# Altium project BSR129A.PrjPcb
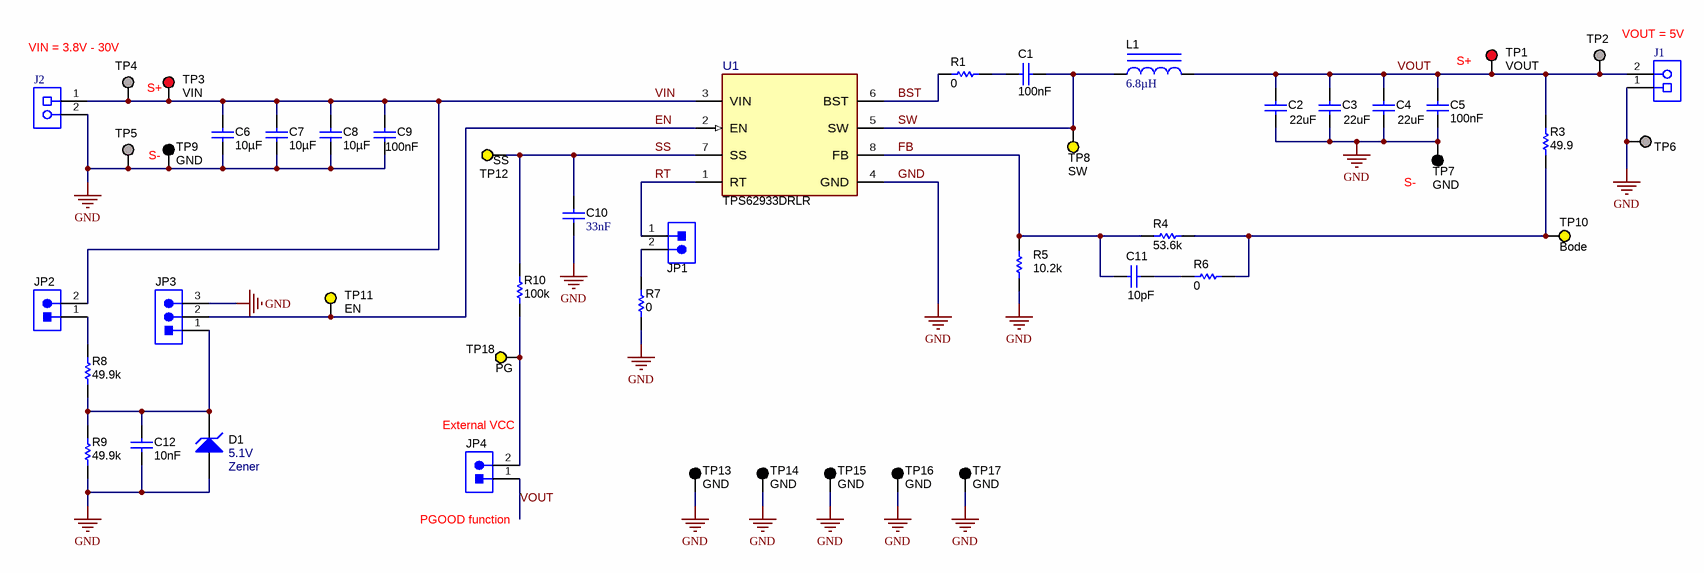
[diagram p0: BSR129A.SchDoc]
A: A; CopyrightYear: 2021; PCB_Layout: Ruby Li; PCB_Rev: A; PRJ_Customer: Public Release; PRJ_Engineer: Ruby Li; PRJ_Number: BSR129; PRJ_Title: BSR129; TechSupport: http://www.ti.com/support; TID: A0489755
2 sheets, 65 parts. Net scope: global (net labels, ports and power ports of the same name join across sheets).
Board file: BSR129A.PcbDoc
Sheets:
  BSR129A.SchDoc
  BSR129A_Hardware.SchDoc

## Sheet BSR129A.SchDoc
size 431 x 279 mm; Date: Not shown in title block; ApprovedBy: Not shown in title block; CheckedBy: Not shown in title block; Author: Not shown in title block; CompanyName: Not shown in title block; Engineer: Not shown in title block; Organization: Not shown in title block; Address1: Not shown in title block; Address2: Not shown in title block; Address3: Not shown in title block; Address4: Not shown in title block; DocumentNumber: 1; Revision: Use project parameter SCH_Rev; SheetNumber: 2; SheetTotal: 3; PageSetup: Record=PageOptions¦CenterHorizontal=True¦CenterVertical=True¦PrintScale=1.00¦XCorrection=1.00¦YCorrection=1.00¦PrintKind=0¦BorderSize=5000000¦LeftOffset=0¦BottomOffset=0¦Orientation=2¦PaperLength=1000¦PaperWidth=1000¦Scale=100¦PaperSource=15¦PrintQuality=600¦MediaType=1¦DitherType=10¦PaperKind=Letter¦PrintScaleMode=1

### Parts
C1  Cap_F: 100nF  [0603]  (hidden comment: C0603C104K5RACAUTO)
C2  ValueDisplayed: 22uF  [1206_180]  (hidden comment: C3216X5R1V226M160AC)
C3  ValueDisplayed: 22uF  [1206_180]  (hidden comment: C3216X5R1V226M160AC)
C4  ValueDisplayed: 22uF  [1206_180]  (hidden comment: C3216X5R1V226M160AC)
C5  Cap_F: 100nF  [0603]  (hidden comment: C0603C104K5RACAUTO)
C6  ValueDisplayed: 10µF  [1206_190]  (hidden comment: CGA5L1X7R1H106K160AC)
C7  ValueDisplayed: 10µF  [1206_190]  (hidden comment: CGA5L1X7R1H106K160AC)
C8  ValueDisplayed: 10µF  [1206_190]  (hidden comment: CGA5L1X7R1H106K160AC)
C9  Cap_F: 100nF  [0603]  (hidden comment: C0603C104K5RACAUTO)
C10  Cap_F: 33nF  [0603]  (hidden comment: 06035C333JAT2A)
C11  ValueDisplayed: 10pF  [0603]  (hidden comment: C0603C100J5GACTU)
C12  Cap_F: 10nF  [0603]  (hidden comment: C0603C103J5RACTU)
D1  Zener  value 5.1V  [SOD-323]
J1  ED120/2DS  [On-Shore_ED120_2DS]  (value not drawn)
J2  ED120/2DS  [On-Shore_ED120_2DS]  (value not drawn)
JP1  PBC02SAAN  [Sullins_PBC02SAAN]  (value not drawn)
JP2  PBC02SAAN  [Sullins_PBC02SAAN]  (value not drawn)
JP3  PEC03SAAN  [CONN_PEC03SAAN]  (value not drawn)
JP4  PBC02SAAN  [Sullins_PBC02SAAN]  (value not drawn)
L1  ValueDisplayed: 6.8µH  [WE-XHMI_6060]  (hidden comment: 74439346068)
R1  ValueDisplayed: 0  [0603]  (hidden comment: RC0603JR-070RL)
R3  ValueDisplayed: 49.9  [0603]  (hidden comment: RC0603FR-0749R9L)
R4  ValueDisplayed: 53.6k  [0603]  (hidden comment: RC0603FR-0753K6L)
R5  ValueDisplayed: 10.2k  [0603]  (hidden comment: RC0603FR-0710K2L)
R6  ValueDisplayed: 0  [0603]  (hidden comment: RC0603JR-070RL)
R7  ValueDisplayed: 0  [0603]  (hidden comment: RC0603JR-070RL)
R8  ValueDisplayed: 49.9k  [0603]  (hidden comment: RC0603FR-0749K9L)
R9  ValueDisplayed: 49.9k  [0603]  (hidden comment: RC0603FR-0749K9L)
R10  ValueDisplayed: 100k  [0603]  (hidden comment: RC0603FR-07100KL)
TP1  VOUT  [Keystone5010]
TP2  1502-2  [Keystone1502-2]  (value not drawn)
TP3  VIN  [Keystone5010]
TP4  1502-2  [Keystone1502-2]  (value not drawn)
TP5  1502-2  [Keystone1502-2]  (value not drawn)
TP6  1502-2  [Keystone1502-2]  (value not drawn)
TP7  GND  [Keystone5011]
TP8  SW  [Keystone5014]
TP9  GND  [Keystone5011]
TP10  Bode  [Keystone5014]
TP11  EN  [Keystone5014]
TP12  SS  [Keystone5014]
TP13  GND  [Keystone5011]
TP14  GND  [Keystone5011]
TP15  GND  [Keystone5011]
TP16  GND  [Keystone5011]
TP17  GND  [Keystone5011]
TP18  PG  [Keystone5014]
U1  TPS62933DRLR  [DRL0008A-MFG]

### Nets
GND: C2.2 C3.2 C4.2 C5.2 C6.2 C7.2 C8.2 C9.2 C10.2 C12.2 D1.2(A) J1.1 J2.2 JP3.3 R5.1 R7.1 R9.1 TP5.1 TP6.1 TP7.1 TP9.1 TP13.1 TP14.1 TP15.1 TP16.1 TP17.1 U1.4(GND)
BST: R1.1 U1.6(BST)
EN: JP3.2 TP11.1 U1.2(EN)
FB: C11.2 R4.1 R5.2 U1.8(FB)
RT: JP1.1 U1.1(RT)
SS: C10.1 R10.2 TP12.1 U1.7(SS)
SW: C1.1 L1.1 TP8.1 U1.5(SW)
VIN: C6.1 C7.1 C8.1 C9.1 J2.1 JP2.2 TP3.1 TP4.1 U1.3(VIN)
VOUT: C2.1 C3.1 C4.1 C5.1 J1.2 JP4.1 L1.2 R3.2 TP1.1 TP2.1
NetC1_2: C1.2 R1.2
NetC11_1: C11.1 R6.1
NetC12_1: C12.1 D1.1(K) JP3.1 R8.1 R9.2
NetJP1_2: JP1.2 R7.2
NetJP2_1: JP2.1 R8.2
NetJP4_2: JP4.2 R10.1 TP18.1
NetR3_1: R3.1 R4.2 R6.2 TP10.1

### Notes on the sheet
- VIN = 3.8V - 30V
- (near TP3) S+
- (near TP1) S+
- VOUT = 5V
- (near TP9) S-
- (near TP7) S-
- (near JP4) External VCC
- (near JP4) PGOOD function

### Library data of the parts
C1 C5 C9 = CMP-0079602-1: CAP, CERM, 0.1 µF, 50 V,+/- 10%, X7R, AEC-Q200 Grade 1, 0603; Manufacturer: Kemet; TaMin_C: -55°C; Polarized: N; SizeAreaWB_mm2: 4.68; U/M: EA; Value: 0.1uF; TaMax_C: 125°C; SizeZ_mm: 1; SizeX_mm: 1.6; SizeY_mm: 0.8; Value2: 50V; SizeArea_mm2: 1.28; AEC Qualified: Y; AEC Category: Q200; ValueDisplayed: 0.1µF
C2-C4 = CMP-0008667-2: CAP, CERM, 22 uF, 35 V, +/- 20%, X5R, 1206; Manufacturer: TDK; TaMin_C: -55°C; ESR_ohm: 2.398m; Polarized: N; SizeAreaWB_mm2: 10.92; Value1: 0.002398 ohm; U/M: EA; Value: 22uF; TaMax_C: 85°C; SizeZ_mm: 1.8; SizeX_mm: 3.2; SizeY_mm: 1.6; Value2: 35V; SizeArea_mm2: 5.12; Cap_F: 22µF; IRMS_A: 4.68507A; AEC Category: Q200
C6-C8 = CMP-0085950-1: CAP, CERM, 10 µF, 50 V,+/- 10%, X7R, AEC-Q200 Grade 1, 1206; Manufacturer: TDK; SizeZ_mm: 1.9; Value: 10uF; Value2: 50V; Cap_Case: 1206; AEC Grade: 1; TaMin_C: -55°C; U/M: EA; SizeArea_mm2: 5.12; TaMax_C: 125°C; AEC Qualified: Y; AEC Category: Q200; SizeX_mm: 3.2; SizeY_mm: 1.6; Polarized: N; SizeAreaWB_mm2: 10.92
C10 = CMP-0006806-1: CAP, CERM, 0.033 uF, 50 V, +/- 5%, X7R, 0603; Manufacturer: AVX; TaMin_C: -55°C; Polarized: N; SizeAreaWB_mm2: 4.68; Value1: Unknown; U/M: EA; TaMax_C: 125°C; SizeZ_mm: 1; SizeX_mm: 1.6; SizeY_mm: 0.8; Value2: 50V; SizeArea_mm2: 1.28; AEC Category: Q200
C11 = CMP-0006839-4: CAP, CERM, 10 pF, 50 V, +/- 5%, C0G/NP0, 0603; Manufacturer: Kemet; TaMin_C: -55°C; Polarized: N; SizeAreaWB_mm2: 4.68; Value1: Unknown; U/M: EA; Value: 10pF; TaMax_C: 125°C; SizeZ_mm: 1; SizeX_mm: 1.6; SizeY_mm: 0.8; Value2: 50V; SizeArea_mm2: 1.28; AEC Category: Q200
C12 = CMP-0006850-4: CAP, CERM, 0.01 uF, 50 V, +/- 5%, X7R, 0603; Manufacturer: Kemet; TaMin_C: -55°C; Polarized: N; SizeAreaWB_mm2: 4.68; Value1: Unknown; U/M: EA; Value: 0.01uF; TaMax_C: 125°C; SizeZ_mm: 1; SizeX_mm: 1.6; SizeY_mm: 0.8; Value2: 50V; SizeArea_mm2: 1.28; AEC Category: Q200
D1 = CMP-0005854-3: Diode, Zener, 5.1 V, 200 mW, SOD-323; PartNumber: MMSZ5231BS-7-F; Manufacturer: Diodes Inc.; Power_W: 200mW; Value1: 0.2W; RJA_CperW: 350; SizeAreaWB_mm2: 8.695; SizeArea_mm2: 3.645; SizeX_mm: 2.7; SizeY_mm: 1.35; SizeZ_mm: 1; AEC Category: Q101
J1 J2 = CMP-0074910-1: Terminal Block, 5.08 mm, 2x1, Brass, TH; Manufacturer: On-Shore Technology; Pitch_mm: 5.08; Gender: Female; Shrouded: N; Row_Count: 1; Current_A: 15A; Voltage_V: 300V; Cert_CULUS: Y; CNHeader: False; CT: True; Green_Lifecycle: Not Set; Green_REACh: Incomplete
JP1 JP2 JP4 = CMP-0054566-1: Header, 100mil, 2x1, Gold, TH; Manufacturer: Sullins Connector Solutions; CNHeader: TRUE; Current_A: 3A; Green_Lifecycle: Active; Shrouded: N; Gender: Male; Green_REACh: Passed; Voltage_V: 1.8kV; Row_Count: 1; Pitch_mm: 2.54; CT: FALSE; Cert_UL: Y
JP3 = CMP-0002338-1: Header, 100mil, 3x1, Tin, TH; Manufacturer: Sullins Connector Solutions; Pitch_mm: 2.54; Gender: Male; Shrouded: N; Row_Count: 1; Current_A: 3A; Voltage_V: 1.8kV; Cert_UL: Y; CNHeader: TRUE; CT: FALSE; Green_Lifecycle: Not Set; Green_REACh: Incomplete
L1 = CMP-0085369-1: Inductor, Shielded, Hyperflux, 6.8 µH, 6.5 A, 0.01936 ohm, SMD; Manufacturer: Wurth Elektronik; AEC Category: Q200; Imax_A: 6.5A; SizeY_mm: 6.45; Isat: 10A @ 30% inductance drop; SizeArea_mm2: 42.8925; Irms: 6.5A @ 40C rise; SizeX_mm: 6.65; Value: 6.8uH; AEC Qualified: N; SizeZ_mm: 6.1; SizeAreaWB_mm2: 73.0925
R1 R6 R7 = CMP-0025885-5: RES, 0, 5%, 0.1 W, 0603; Manufacturer: Yageo; Power_W: 100mW; TempCo: 200 ppm/C; Value_Code: 0000; Value: 0; EIA_Code: E24; SizeX_mm: 1.6; SizeZ_mm: 1; Value2: 0.1W; SizeArea_mm2: 1.28; AEC Qualified: N; VDC_V: 75V; AEC Category: Q200; SizeY_mm: 0.8; SizeAreaWB_mm2: 4.68
R3 = CMP-0023143-5: RES, 49.9, 1%, 0.1 W, 0603; Manufacturer: Yageo; Power_W: 100mW; TempCo: 100 ppm/C; Value_Code: 49R9; Value: 49.9; EIA_Code: E96; SizeX_mm: 1.6; SizeY_mm: 0.8; SizeZ_mm: 1; Value2: 0.1W; SizeArea_mm2: 1.28; AEC Qualified: N; VDC_V: 75V; AEC Category: Q200; SizeAreaWB_mm2: 4.68
R4 = CMP-0023176-5: RES, 53.6 k, 1%, 0.1 W, 0603; Manufacturer: Yageo; Power_W: 100mW; TempCo: 100 ppm/C; Value_Code: 53k6; Value: 53.6k; EIA_Code: E96; SizeX_mm: 1.6; SizeY_mm: 0.8; SizeZ_mm: 1; Value2: 0.1W; SizeArea_mm2: 1.28; AEC Qualified: N; VDC_V: 75V; AEC Category: Q200; SizeAreaWB_mm2: 4.68
R5 = CMP-0022743-5: RES, 10.2 k, 1%, 0.1 W, 0603; Manufacturer: Yageo; Power_W: 100mW; TempCo: 100 ppm/C; Value_Code: 10k2; Value: 10.2k; EIA_Code: E96; SizeX_mm: 1.6; SizeY_mm: 0.8; SizeZ_mm: 1; Value2: 0.1W; SizeArea_mm2: 1.28; AEC Qualified: N; VDC_V: 75V; AEC Category: Q200; SizeAreaWB_mm2: 4.68
R8 R9 = CMP-0023142-5: RES, 49.9 k, 1%, 0.1 W, 0603; Manufacturer: Yageo; Power_W: 100mW; TempCo: 100 ppm/C; Value_Code: 49k9; Value: 49.9k; EIA_Code: E96; SizeX_mm: 1.6; SizeY_mm: 0.8; SizeZ_mm: 1; Value2: 0.1W; SizeArea_mm2: 1.28; AEC Qualified: N; VDC_V: 75V; AEC Category: Q200; SizeAreaWB_mm2: 4.68
R10 = CMP-0022735-5: RES, 100 k, 1%, 0.1 W, 0603; Manufacturer: Yageo; Power_W: 100mW; TempCo: 100 ppm/C; Value: 100k; EIA_Code: E96; SizeX_mm: 1.6; SizeY_mm: 0.8; SizeZ_mm: 1; Value2: 0.1W; SizeArea_mm2: 1.28; AEC Qualified: N; VDC_V: 75V; AEC Category: Q200; SizeAreaWB_mm2: 4.68
TP1 TP3 = CMP-0055147-1: Test Point, Multipurpose, Red, TH; Manufacturer: Keystone; PartNumber: 5010; CNHeader: FALSE; Green_Lifecycle: Active; Green_REACh: Passed; ContactFinish: Silver; CT: TRUE
TP2 TP4-TP6 = CMP-0055113-1: Terminal, Turret, TH, Double; Manufacturer: Keystone; CompType: Turret Terminal; CNHeader: FALSE; Green_Lifecycle: Active; Green_REACh: Passed
TP7 TP9 TP13-TP17 = CMP-0055148-1: Test Point, Multipurpose, Black, TH; Manufacturer: Keystone; PartNumber: 5011; CNHeader: FALSE; Green_Lifecycle: Active; Green_REACh: Passed; ContactFinish: Silver; CT: TRUE
TP8 TP10-TP12 TP18 = CMP-0055151-1: Test Point, Multipurpose, Yellow, TH; Manufacturer: Keystone; PartNumber: 5014; CNHeader: FALSE; Green_Lifecycle: Active; Green_REACh: Passed; ContactFinish: Silver; CT: TRUE
U1 = CMP-0090998-1: 3.8-V to 30-V Input, 3-A/2-A, 300kHz-2.2MHz, Low IQ Synchronous Buck Converter in SOT583 Package; Manufacturer: Texas Instruments; Output Voltage: 0.8-22V; Max Supply Voltage: 30V; TJmax_C: +150°C; Max Duty Cycle: 98%; AEC Qualified: No; Switching Frequency: 310-2100kHz; Output Type: AdjustableProgrammable; Number Of Outputs: 1; SizeZ_mm: 0.6mm; Min Supply Voltage: 3.8V; Standoff Height: 0mm; Nominal Supply Current: 12-250uA

## Sheet BSR129A_Hardware.SchDoc
size 431 x 279 mm; Date: Not shown in title block; ApprovedBy: Not shown in title block; CheckedBy: Not shown in title block; Author: Not shown in title block; CompanyName: Not shown in title block; Engineer: Not shown in title block; Organization: Not shown in title block; Address1: Not shown in title block; Address2: Not shown in title block; Address3: Not shown in title block; Address4: Not shown in title block; DocumentNumber: 1; Revision: Use project parameter SCH_Rev; SheetNumber: 1; SheetTotal: 2; PageSetup: Record=PageOptions¦CenterHorizontal=True¦CenterVertical=True¦PrintScale=1.00¦XCorrection=1.00¦YCorrection=1.00¦PrintKind=0¦BorderSize=5000000¦LeftOffset=0¦BottomOffset=0¦Orientation=2¦PaperLength=1000¦PaperWidth=1000¦Scale=100¦PaperSource=15¦PrintQuality=600¦MediaType=1¦DitherType=10¦PaperKind=Letter¦PrintScaleMode=1
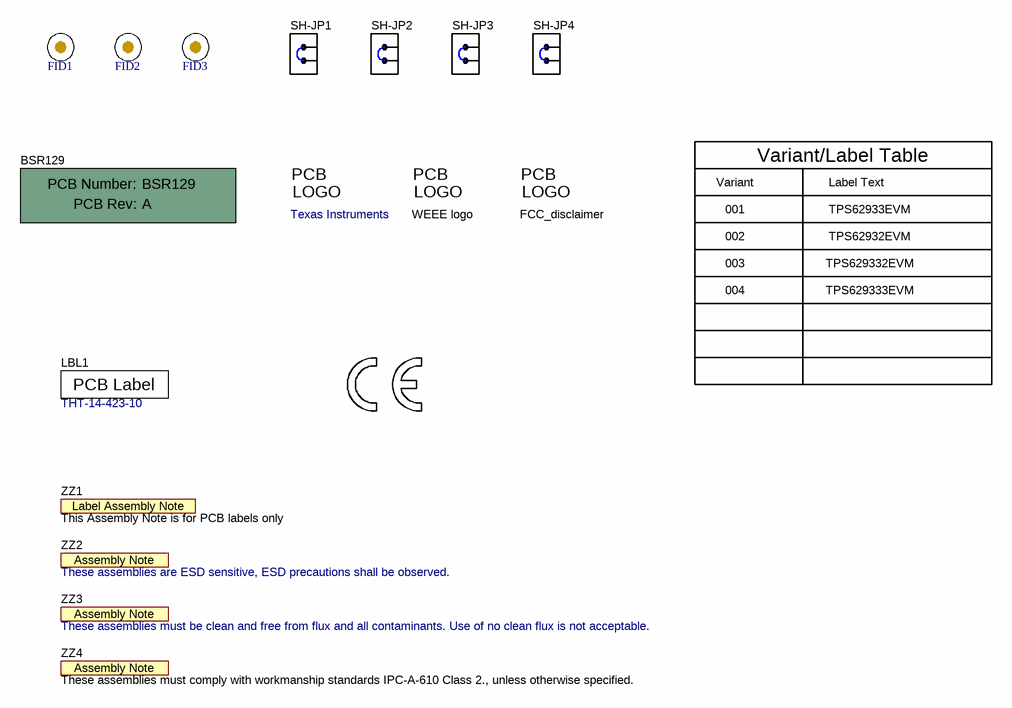
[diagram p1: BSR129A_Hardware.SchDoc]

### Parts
!PCB1  PartNumber: BSR129  (hidden comment: Printed Circuit Board)  (mechanical)
FID1  Fiducial  [Fiducial10-20]  (value not drawn)
FID2  Fiducial  [Fiducial10-20]  (value not drawn)
FID3  Fiducial  [Fiducial10-20]  (value not drawn)
LBL1  THT-14-423-10  [Label_650x200]
Logo1  Texas Instruments  [TI_Stacked_Overlay_Small]  (no BOM)
Logo2  WEEE logo  [WEEE_Minimum]  (no BOM)
Logo3  FCC disclaimer  [FCC_disclaimer]  (value not drawn)  (no BOM)
LOGO4  CE Mark  [CE_Mark_5mm]  (value not drawn)  (no BOM)
SH-JP1  SNT-100-BK-G  [SNT-100-BK-G]  (value not drawn)
SH-JP2  SNT-100-BK-G  [SNT-100-BK-G]  (value not drawn)
SH-JP3  SNT-100-BK-G  [SNT-100-BK-G]  (value not drawn)
SH-JP4  SNT-100-BK-G  [SNT-100-BK-G]  (value not drawn)
ZZ1  This Assembly Note is for PCB labels only  [AssemblyNoteLabel]  (no BOM)
ZZ2  These assemblies are ESD sensitive, ESD precautions shall be observed.  [AssemblyNote]  (no BOM)
ZZ3  These assemblies must be clean and free from flux and all contaminants. Use of no clean flux is not acceptable.  [AssemblyNote]  (no BOM)
ZZ4  These assemblies must comply with workmanship standards IPC-A-610 Class 2., unless otherwise specified.  [AssemblyNote]  (no BOM)

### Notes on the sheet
- Variant
- 001
- Variant/Label Table
- Label Text
- TPS62933EVM
- 002
- 003
- TPS629332EVM
- TPS62932EVM
- 004
- TPS629333EVM

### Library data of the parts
!PCB1 = CMP-0003618-2: Manufacturer: Any
FID1-FID3 = CMP-0077181-1: Fiducial mark.  There is nothing to buy or mount.
LBL1 = CMP-0003625-1: Thermal Transfer Printable Labels, 0.650" W x 0.200" H - 10,000 per roll; Manufacturer: Brady; Note: Size: 0.65" x 0.20 "
Logo1 = CMP-0074838-1: Texas Instrument Corporate Signature; SymbolCreator: a0412235; Lib Reference: TI_Logo
Logo2 = CMP-0074769-1
Logo3 = CMP-0074847-1: FCC_disclaimer; Library Reference: Logo
LOGO4 = CMP-0074844-1: SymbolCreator: a0412235
SH-JP1-SH-JP4 = CMP-0003623-3: Shunt, 100mil, Gold plated, Black; Alternate PartNumber: 969102-0000-DA; Manufacturer: Samtec; Alternate Manufacturer: 3M; Value: 1x2; Note: You can "mate" this to a header by matching the designator.  i.e. use SH-J3 for header J3
ZZ1 = CMP-0003616-3
ZZ2 = CMP-0077236-1
ZZ3 = CMP-0077237-1
ZZ4 = AssemblyNote: SymbolCreator: codlsc

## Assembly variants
001: not fitted C4 C6 C11 FID1 FID2 FID3 JP4 R10 SH-JP4 TP18; alternate parts L1 -> CMP-0085369-1, U1 -> CMP-0090998-1
002: not fitted C4 C6 C10 C11 FID1 FID2 FID3 TP12
003: not fitted C4 C6 C11 FID1 FID2 FID3
004: not fitted C4 C6 C11 FID1 FID2 FID3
